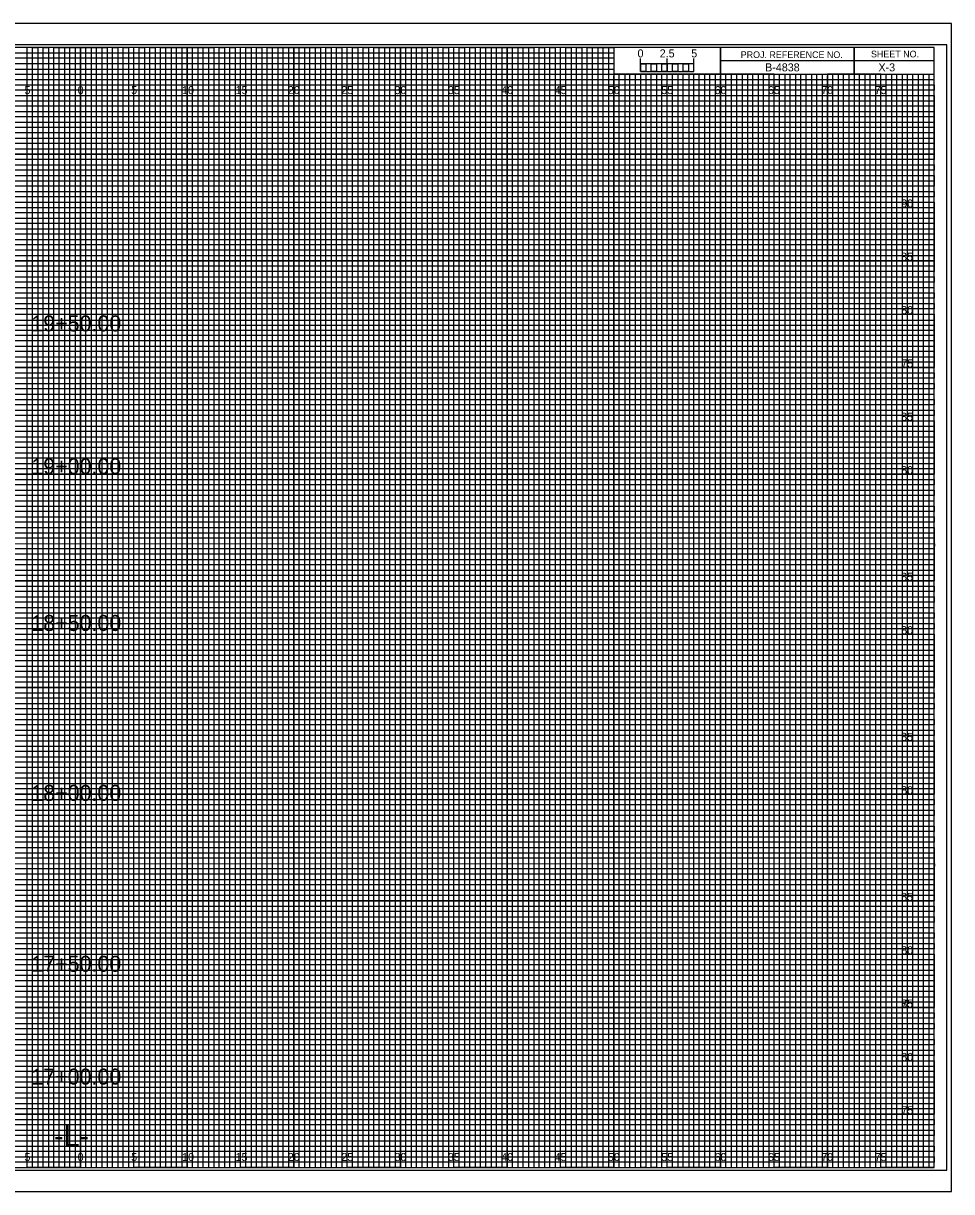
# Model space of a CAD drawing. Extents: x -7 to 182, y -2 to 1647.
# Drawn here: x 74.6 to 161.7, y 107.7 to 217.2 of the extents above; entities that cross this region are included whole.
import ezdxf

# ---------------------------------------------------------------- set-up
doc = ezdxf.new("R2010")
doc.units = 0
for name, color, linetype in [('Exist CMT Pavement', 7, 'Continuous'), ('Exist Cross Section Cell', 7, 'Continuous'), ('Exist XS Ground Line', 7, 'Continuous'), ('Prop CMT Pvmt Course 1', 7, 'Continuous'), ('Prop CMT Pvmt Course 2', 7, 'Continuous'), ('Prop CMT Pvmt Course 2 Wedge', 7, 'Continuous'), ('Prop CMT Pvmt Course 3', 7, 'Continuous'), ('Prop CMT Pvmt Surface', 7, 'Continuous'), ('Prop CMT Pvmt Surface Shoulder', 7, 'Continuous'), ('Prop CMT Pvmt Wedge Surface 1', 7, 'Continuous'), ('Prop CMT Pvmt Wedge Surface 2', 7, 'Continuous'), ('Prop CMT Pvmt Wedge Surface 3', 7, 'Continuous'), ('Prop CMT Shld Paved Course 1', 7, 'Continuous'), ('Prop CMT Shld Paved Course 2', 7, 'Continuous'), ('Prop CMT Shld Paved Course 3', 7, 'Continuous'), ('Prop CMT Slope Grass', 7, 'Continuous'), ('Prop CMT Subgrade Earthwork', 7, 'Continuous')]:
    doc.layers.add(name, color=color, linetype=linetype)

msp = doc.modelspace()

# ---------------------------------------------------------------- linework, layer by layer
at = {"layer": 'Exist XS Ground Line'}
for p, q in [((75, 215), (70, 215)), ((75, 110), (75, 215)), ((85, 215), (80, 215)), ((80, 215), (80, 110)), ((85, 110), (85, 215)), ((95, 215), (90, 215)), ((90, 215), (90, 110)), ((95, 110), (95, 215)), ((105, 215), (100, 215)), ((100, 215), (100, 110)), ((105, 110), (105, 215)), ((115, 215), (110, 215)), ((110, 215), (110, 110)), ((115, 110), (115, 215)), ((125, 215), (120, 215)), ((120, 215), (120, 110)), ((125, 110), (125, 215)), ((130, 215), (130, 110)), ((135, 110), (135, 212.5)), ((145, 212.5), (140, 212.5)), ((140, 212.5), (140, 110)), ((145, 110), (145, 212.5)), ((155, 212.5), (150, 212.5)), ((150, 212.5), (150, 110)), ((155, 110), (155, 212.5)), ((80, 110), (75, 110)), ((90, 110), (85, 110)), ((100, 110), (95, 110)), ((110, 110), (105, 110)), ((120, 110), (115, 110)), ((130, 110), (125, 110)), ((140, 110), (135, 110)), ((150, 110), (145, 110)), ((160, 110), (155, 110)), ((160, 110), (160, 110))]:
    msp.add_line(p, q, dxfattribs=at)
for points in [[(0, 210), (160, 210), (160, 205), (0, 205)], [(0, 200), (160, 200), (160, 195), (0, 195)], [(0, 190), (160, 190), (160, 185), (0, 185)], [(0, 180), (160, 180), (160, 175), (0, 175)], [(0, 170), (160, 170), (160, 165), (0, 165)], [(0, 160), (160, 160), (160, 155), (0, 155)], [(0, 150), (160, 150), (160, 145), (0, 145)], [(0, 140), (160, 140), (160, 135), (0, 135)], [(0, 130), (160, 130), (160, 125), (0, 125)], [(0, 120), (160, 120), (160, 115), (0, 115)]]:
    msp.add_lwpolyline(points, dxfattribs=at)
at = {"layer": 'Prop CMT Pvmt Course 2'}
for p, q in [((132.5, 212.75), (132.5, 213.95)), ((132.5, 213.45), (132.5, 213.95)), ((135, 212.75), (135, 213.95)), ((137.5, 212.75), (137.5, 213.95)), ((137.5, 213.45), (137.5, 213.95))]:
    msp.add_line(p, q, dxfattribs=at)
for points in [[(137.5, 213.45), (132.5, 213.45), (132.5, 212.75), (137.5, 212.75)], [(132.5, 213.45), (133, 213.45), (133, 212.75), (132.5, 212.75)], [(133.5, 213.45), (134, 213.45), (134, 212.75), (133.5, 212.75)], [(134.5, 213.45), (135, 213.45), (135, 212.75), (134.5, 212.75)], [(135.5, 213.45), (136, 213.45), (136, 212.75), (135.5, 212.75)], [(136.5, 213.45), (137, 213.45), (137, 212.75), (136.5, 212.75)]]:
    msp.add_lwpolyline(points, close=True, dxfattribs=at)
at = {"layer": 'Prop CMT Pvmt Course 3'}
msp.add_lwpolyline([(-6.7, 107.75), (161.65, 107.75), (161.65, 217.25), (-6.7, 217.25)], close=True, dxfattribs=at)
at = {"layer": 'Prop CMT Pvmt Wedge Surface 1'}
for p, q in [((0, 214.5), (130, 214.5)), ((130, 213.99), (0, 213.99)), ((130, 214.5), (130, 213.99)), ((0, 213.5), (130, 213.5)), ((130, 212.94), (0, 212.94)), ((130, 213.5), (130, 212.94)), ((0, 212), (160, 212))]:
    msp.add_line(p, q, dxfattribs=at)
for points in [[(0, 211.5), (135, 211.5), (160, 211.5), (160, 211), (0, 211)], [(0, 210.5), (160, 210.5), (160, 209.5), (0, 209.5)], [(0, 209), (160, 209), (160, 208.5), (0, 208.49)], [(0, 208), (160, 208), (160, 207), (0, 207)], [(0, 206.5), (160, 206.5), (160, 206), (0, 206)], [(0, 205.5), (160, 205.5), (160, 204.5), (0, 204.5)], [(0, 204), (160, 204), (160, 203.5), (0, 203.5)], [(0, 203), (160, 203), (160, 202), (0, 202)], [(0, 201.5), (160, 201.5), (160, 201), (0, 201)], [(0, 200.5), (160, 200.5), (160, 199.5), (0, 199.5)], [(0, 199), (160, 199), (160, 198.5), (0, 198.5)], [(0, 198), (160, 198), (160, 196.97), (160, 196.5), (160, 196), (0, 196)], [(0, 197), (160, 197), (160, 196.5), (0, 196.5)], [(0, 195.5), (160, 195.5), (160, 194.5), (0, 194.52)], [(0, 194.52), (160, 194.5), (160, 194), (0, 194)], [(0, 193.5), (160, 193.5), (160, 193), (0, 193)], [(0, 192), (160, 192), (160, 191.5), (0, 191.5)], [(0, 191), (160, 191), (160, 190.5), (0, 190.5)], [(-0.04, 189.44), (160, 189.44), (160, 188.94), (-0.04, 188.94)], [(0, 188.5), (160, 188.5), (160, 188), (0, 188)], [(0, 187), (160, 187), (160, 186.5), (0, 186.5)], [(0, 186), (160, 186), (160, 185.5), (0, 185.5)], [(0, 184.5), (160, 184.5), (160, 184), (0, 184)], [(0, 183.5), (160, 183.5), (160, 183), (0, 183)], [(0, 182), (160, 182), (160, 181.5), (0, 181.5)], [(0, 181), (160, 181), (160, 180.5), (0, 180.5)], [(0, 179.5), (160, 179.5), (160, 178.99), (0, 179)], [(0, 178.5), (160, 178.5), (160, 178), (0, 178)], [(0, 177), (160, 177), (160, 176.5), (0, 176.5)], [(0, 176), (160, 176), (160, 175.5), (0, 175.5)], [(0, 174.5), (160, 174.5), (160, 174), (0, 174)], [(0, 173.5), (160, 173.5), (160, 173), (0, 173)], [(0, 172), (160, 172), (160, 171.5), (0, 171.5)], [(0, 171), (160, 171), (160, 170.5), (0, 170.5)], [(0, 169.5), (160, 169.5), (160, 169), (0, 169)], [(0, 168.5), (160.03, 168.46), (160, 168), (0, 168)], [(0, 167), (160, 167), (160, 166.5), (0, 166.5)], [(0, 166), (160, 166), (160, 165.5), (0, 165.5)], [(0, 164.5), (160, 164.5), (160, 164), (0, 164)], [(0, 163.5), (160, 163.5), (160, 163), (0, 163)], [(0, 162), (160, 162), (160, 161.5), (0, 161.5)], [(0, 161), (160, 161), (160, 160.5), (0, 160.5)], [(0, 159.5), (160, 159.5), (160, 159), (0, 159)], [(0, 158.5), (160, 158.5), (160, 158), (0, 158)], [(0, 157), (160, 157), (160, 156.5), (0, 156.5)], [(0, 156), (160, 156), (160, 155.5), (0, 155.5)], [(0, 154.5), (160, 154.5), (160, 154), (0, 154)], [(0, 153.5), (160, 153.5), (160, 153), (0, 153)], [(0, 152), (160, 152), (160, 151.5), (0, 151.5)], [(0, 151), (160, 151), (160, 150.5), (0, 150.5)], [(0, 149.5), (160, 149.5), (160, 148.99), (0, 149)], [(0, 148.5), (160, 148.5), (160, 148), (0, 148)], [(0, 147), (160, 147), (160, 146.5), (0, 146.5)], [(0, 146), (160, 146), (160, 145.5), (0, 145.5)], [(0, 144.5), (160, 144.5), (160, 144), (0, 144)], [(0, 143.5), (160, 143.5), (160, 143), (0, 143)], [(0, 142), (160, 142), (160, 141.5), (0, 141.5)], [(0, 141), (160, 141), (160, 140.5), (0, 140.5)], [(0, 139.5), (160, 139.5), (160, 139), (0, 139)], [(0, 138.5), (160.03, 138.46), (160, 138), (0, 138)], [(0, 137), (160, 137), (160, 136.5), (0, 136.5)], [(0, 136), (160, 136), (160, 135.5), (0, 135.5)], [(0, 134.5), (160, 134.5), (160, 134), (0, 134)], [(0, 133.5), (160, 133.5), (160, 133), (0, 133)], [(0, 132), (160, 132), (160, 131.5), (0, 131.5)], [(0, 131), (160, 131), (160, 130.5), (0, 130.5)], [(0, 129.5), (160, 129.5), (160, 129), (0, 129)], [(0, 128.5), (160, 128.5), (160, 128), (0, 128)], [(0, 127), (160, 127), (160, 126.5), (0, 126.5)], [(0, 126), (160, 126), (160, 125.5), (0, 125.5)], [(0, 124.5), (160, 124.5), (160, 124), (0, 124)], [(0, 123.5), (160, 123.5), (160, 123), (0, 123)], [(0, 122), (160, 122), (160, 121.5), (0, 121.5)], [(0, 121), (160, 121), (160, 120.5), (0, 120.5)], [(0, 119.5), (160, 119.5), (160, 119), (0, 119)], [(0, 118.5), (160, 118.5), (160, 118), (0, 118)], [(0, 117), (160, 117), (160, 116.5), (0, 116.5)], [(0, 116), (160, 116), (160, 115.5), (0, 115.5)], [(0, 114.5), (160, 114.5), (160, 114), (0, 114)], [(0, 113.5), (160, 113.5), (160, 113), (0, 113)], [(0, 112), (160, 112), (160, 111.5), (0, 111.5)], [(0, 111), (160, 111), (160, 110.5), (0, 110.5)]]:
    msp.add_lwpolyline(points, dxfattribs=at)
at = {"layer": 'Prop CMT Pvmt Wedge Surface 2'}
for p, q in [((152.5, 215), (152.5, 212.5)), ((152.5, 212.5), (152.5, 215)), ((160, 213.75), (140, 213.75)), ((140, 213.75), (140, 212.5)), ((140, 212.5), (160, 212.5))]:
    msp.add_line(p, q, dxfattribs=at)
for points in [[(160, 215), (0, 215), (0, 110), (160, 110)], [(140, 215), (130, 215), (130, 212.52), (140, 212.52)], [(160, 215), (140, 215), (140, 212.5), (160, 212.5)]]:
    msp.add_lwpolyline(points, close=True, dxfattribs=at)
at = {"layer": 'Prop CMT Pvmt Wedge Surface 3'}
for p, q in [((133.5, 212.5), (133, 212.5)), ((133, 212.5), (133, 110)), ((133.5, 110), (133.5, 212.5)), ((134.5, 212.5), (134, 212.5)), ((134, 212.5), (134, 110)), ((134.5, 110), (134.5, 212.5)), ((133, 110), (132.5, 110)), ((134, 110), (133.5, 110))]:
    msp.add_line(p, q, dxfattribs=at)
for points in [[(75, 110), (75.5, 110), (75.5, 215), (76, 215), (76, 110)], [(76, 110), (76.5, 110), (76.5, 215), (77, 215), (77, 110)], [(77.5, 110), (78, 110), (78, 215), (78.5, 215), (78.5, 110)], [(78.5, 110), (79, 110), (79, 215), (79.5, 215), (79.5, 110)], [(80, 110), (80.5, 110), (80.5, 215), (81, 215), (81, 110)], [(81, 110), (81.5, 110), (81.5, 215), (82, 215), (82, 110)], [(82.5, 110), (83, 110), (83, 215), (83.5, 215), (83.5, 110)], [(83.5, 110), (84, 110), (84, 215), (84.5, 215), (84.5, 110)], [(85, 110), (85.5, 110), (85.5, 215), (86, 215), (86, 110)], [(86, 110), (86.5, 110), (86.5, 215), (87, 215), (87, 110)], [(87.5, 110), (88, 110), (88, 215), (88.5, 215), (88.5, 110)], [(88.5, 110), (89, 110), (89, 215), (89.5, 215), (89.5, 110)], [(90, 110), (90.5, 110), (90.5, 215), (91, 215), (91, 110)], [(91, 110), (91.5, 110), (91.5, 215), (92, 215), (92, 110)], [(92.5, 110), (93, 110), (93, 215), (93.5, 215), (93.5, 110)], [(93.5, 110), (94, 110), (94, 215), (94.5, 215), (94.5, 110)], [(95, 110), (95.5, 110), (95.5, 215), (96, 215), (96, 110)], [(96, 110), (96.5, 110), (96.5, 215), (97, 215), (97, 110)], [(97.5, 110), (98, 110), (98, 215), (98.5, 215), (98.5, 110)], [(98.5, 110), (99, 110), (99, 215), (99.5, 215), (99.5, 110)], [(100, 110), (100.5, 110), (100.5, 215), (101, 215), (101, 110)], [(101, 110), (101.5, 110), (101.5, 215), (102, 215), (102, 110)], [(102.5, 110), (103, 110), (103, 215), (103.5, 215), (103.5, 110)], [(103.5, 110), (104, 110), (104, 215), (104.5, 215), (104.5, 110)], [(105, 110), (105.5, 110), (105.5, 215), (106, 215), (106, 110)], [(106, 110), (106.5, 110), (106.5, 215), (107, 215), (107, 110)], [(107.5, 110), (108, 110), (108, 215), (108.5, 215), (108.5, 110)], [(108.5, 110), (109, 110), (109, 215), (109.5, 215), (109.5, 110)], [(110, 110), (110.5, 110), (110.5, 215), (111, 215), (111, 110)], [(111, 110), (111.5, 110), (111.5, 215), (112, 215), (112, 110)], [(112.5, 110), (113, 110), (113, 215), (113.5, 215), (113.5, 110)], [(113.5, 110), (114, 110), (114, 215), (114.5, 215), (114.5, 110)], [(115, 110), (115.5, 110), (115.5, 215), (116, 215), (116, 110)], [(116, 110), (116.5, 110), (116.5, 215), (117, 215), (117, 110)], [(117.5, 110), (118, 110), (118, 215), (118.5, 215), (118.5, 110)], [(118.5, 110), (119, 110), (119, 215), (119.5, 215), (119.5, 110)], [(120, 110), (120.5, 110), (120.5, 215), (121, 215), (121, 110)], [(121, 110), (121.5, 110), (121.5, 215), (122, 215), (122, 110)], [(122.5, 110), (123, 110), (123, 215), (123.5, 215), (123.5, 110)], [(123.5, 110), (124, 110), (124, 215), (124.5, 215), (124.5, 110)], [(125, 110), (125.5, 110), (125.5, 215), (126, 215), (126, 110)], [(126, 110), (126.5, 110), (126.5, 215), (127, 215), (127, 110)], [(127.5, 110), (128, 110), (128, 215), (128.5, 215), (128.5, 110)], [(128.5, 110), (129, 110), (129, 215), (129.5, 215), (129.5, 110)], [(130, 110), (130.5, 110), (130.5, 212.5), (131.01, 212.5), (131.01, 110)], [(131, 110), (131.5, 110), (131.5, 212.5), (132, 212.5), (132, 110)], [(135, 110), (135.49, 110), (135.49, 212.5), (136, 212.5), (136, 110)], [(136, 110), (136.5, 110), (136.5, 212.5), (137.03, 212.5), (137.03, 110)], [(137.5, 110), (138, 110), (138, 212.5), (138.5, 212.5), (138.5, 110)], [(138.5, 110), (139, 110), (139, 212.5), (139.5, 212.5), (139.5, 110)], [(140, 110), (140.5, 110), (140.5, 212.5), (141, 212.5), (141, 110)], [(141, 110), (141.5, 110), (141.5, 212.5), (142, 212.5), (142, 110)], [(142.5, 110), (143, 110), (143, 212.5), (143.5, 212.5), (143.5, 110)], [(143.5, 110), (144, 110), (144, 212.5), (144.5, 212.5), (144.5, 110)], [(145, 110), (145.5, 110), (145.5, 212.5), (146, 212.5), (146, 110)], [(146, 110), (146.5, 110), (146.5, 212.5), (147, 212.5), (147, 110)], [(147.5, 110), (148, 110), (148, 212.5), (148.5, 212.5), (148.5, 110)], [(148.5, 110), (149, 110), (149, 212.5), (149.5, 212.5), (149.5, 110)], [(150, 110), (150.5, 110), (150.5, 212.5), (151, 212.5), (151, 110)], [(151, 110), (151.5, 110), (151.5, 212.5), (152, 212.5), (152, 110)], [(152.5, 110), (153, 110), (153, 212.5), (153.5, 212.5), (153.5, 110)], [(153.5, 110), (154, 110), (154, 212.5), (154.5, 212.5), (154.5, 110)], [(155, 110), (155.5, 110), (155.5, 212.5), (156, 212.5), (156, 110)], [(156, 110), (156.5, 110), (156.5, 212.5), (157, 212.5), (157, 110)], [(157.5, 110), (158, 110), (158, 212.5), (158.5, 212.5), (158.5, 110)], [(158.5, 110), (159, 110), (159, 212.5), (159.5, 212.5), (159.5, 110)]]:
    msp.add_lwpolyline(points, dxfattribs=at)
at = {"layer": 'Prop CMT Shld Paved Course 1'}
for p, q in [((75, 110), (75, 215)), ((80, 110), (80, 215)), ((85, 110), (85, 215)), ((90, 110), (90, 215)), ((95, 110), (95, 215)), ((100, 110), (100, 215)), ((105, 110), (105, 215)), ((110, 110), (110, 215)), ((115, 110), (115, 215)), ((120, 110), (120, 215)), ((125, 110), (125, 215)), ((130, 110), (130, 212.34)), ((135, 110), (135, 212.34)), ((140, 110), (140, 212.34)), ((145, 110), (145, 212.34)), ((150, 110), (150, 212.34)), ((155, 110), (155, 212.34)), ((0, 210), (160, 210)), ((0, 205), (160, 205)), ((0, 200), (160, 200)), ((0, 195), (160, 195)), ((0, 190), (160, 190)), ((0, 185), (160, 185)), ((0, 180), (160, 180)), ((0, 175), (160, 175)), ((0, 170), (160, 170)), ((0, 165), (160, 165)), ((0, 160), (160, 160)), ((0, 155), (160, 155)), ((0, 150), (160, 150)), ((0, 145), (160, 145)), ((0, 140), (160, 140)), ((0, 135), (160, 135)), ((0, 130), (160, 130)), ((0, 125), (160, 125)), ((0, 120), (160, 120)), ((0, 115), (160, 115))]:
    msp.add_line(p, q, dxfattribs=at)
at = {"layer": 'Prop CMT Shld Paved Course 2'}
for p, q in [((161.65, 217.25), (-6.7, 217.25)), ((-6.7, 107.75), (161.65, 107.75))]:
    msp.add_line(p, q, dxfattribs=at)
at = {"layer": 'Prop CMT Slope Grass'}
msp.add_lwpolyline([(-5.4, 109.75), (161.2, 109.75), (161.2, 215.25), (-5.4, 215.25)], close=True, dxfattribs=at)
at = {"layer": 'Prop CMT Subgrade Earthwork'}
for points in [[(72.5, 110), (77.5, 110), (77.5, 215), (82.5, 215), (82.5, 110), (87.5, 110), (87.5, 215), (92.5, 215), (92.5, 110), (97.5, 110), (97.5, 215), (102.5, 215), (102.5, 110), (107.5, 110), (107.5, 215), (112.5, 215), (112.5, 110), (117.5, 110), (117.5, 215), (122.5, 215), (122.5, 110), (127.5, 110), (127.5, 215), (129.97, 215), (130, 215), (130, 212.5), (132.5, 212.5), (132.5, 110), (137.5, 110), (137.5, 212.5), (142.5, 212.5), (142.5, 110), (147.5, 110), (147.5, 212.5), (152.5, 212.5), (152.5, 110), (157.5, 110), (157.5, 212.5)], [(0, 212.5), (137.5, 212.5)], [(0, 202.5), (160, 202.5), (160, 207.5), (0, 207.5)], [(0, 192.5), (160, 192.5), (160, 197.5), (0, 197.5)], [(0, 182.5), (160, 182.5), (160, 187.5), (0, 187.5)], [(0, 172.5), (160, 172.5), (160, 177.5), (0, 177.5)], [(0, 162.5), (160, 162.5), (160, 167.5), (0, 167.5)], [(0, 152.5), (160, 152.5), (160, 157.5), (0, 157.5)], [(0, 142.5), (160, 142.5), (160, 147.5), (0, 147.5)], [(0, 132.5), (160, 132.5), (160, 137.5), (0, 137.5)], [(0, 122.5), (160, 122.5), (160, 127.5), (0, 127.5)], [(0, 112.5), (160, 112.5), (160, 117.5), (0, 117.5)]]:
    msp.add_lwpolyline(points, dxfattribs=at)

# ---------------------------------------------------------------- texts
at = {"layer": 'Exist CMT Pavement'}
for s, p in [('19+50.00', (75.39, 188.38)), ('19+00.00', (75.39, 174.99)), ('18+50.00', (75.39, 160.3)), ('18+00.00', (75.39, 144.37)), ('17+50.00', (75.39, 128.36)), ('17+00.00', (75.39, 117.78))]:
    msp.add_text(s, height=1.5, dxfattribs=at).set_placement(p)
at = {"layer": 'Exist Cross Section Cell'}
for s, p in [('5', (74.74, 210.62)), ('0', (79.73, 210.62)), ('0', (79.73, 210.62)), ('5', (84.74, 210.62)), ('10', (89.52, 210.62)), ('15', (94.53, 210.62)), ('20', (99.43, 210.62)), ('25', (104.44, 210.62)), ('30', (109.43, 210.62)), ('35', (114.44, 210.62)), ('40', (119.43, 210.62)), ('45', (124.44, 210.62)), ('50', (129.43, 210.62)), ('55', (134.44, 210.62)), ('60', (139.43, 210.62)), ('65', (144.44, 210.62)), ('70', (149.43, 210.62)), ('75', (154.44, 210.62)), ('5', (74.74, 110.62)), ('0', (79.73, 110.62)), ('0', (79.73, 110.62)), ('5', (84.74, 110.62)), ('10', (89.52, 110.62)), ('15', (94.53, 110.62)), ('20', (99.43, 110.62)), ('25', (104.44, 110.62)), ('30', (109.43, 110.62)), ('35', (114.44, 110.62)), ('40', (119.43, 110.62)), ('45', (124.44, 110.62)), ('50', (129.43, 110.62)), ('55', (134.44, 110.62)), ('60', (139.43, 110.62)), ('65', (144.44, 110.62)), ('70', (149.43, 110.62)), ('75', (154.44, 110.62))]:
    msp.add_text(s, height=0.75, dxfattribs=at).set_placement(p)
at = {"layer": 'Prop CMT Pvmt Course 1'}
msp.add_text('-L-', height=2, dxfattribs=at).set_placement((77.53, 112))
at = {"layer": 'Prop CMT Pvmt Course 2'}
msp.add_text('0', height=0.75, dxfattribs=at).set_placement((132.21, 214.06))
at = {"layer": 'Prop CMT Pvmt Course 2 Wedge'}
for s, p in [('2.5', (134.29, 214.06)), ('5', (137.24, 214.06))]:
    msp.add_text(s, height=0.75, dxfattribs=at).set_placement(p)
at = {"layer": 'Prop CMT Pvmt Surface'}
msp.add_text('X-3', height=0.75, dxfattribs=at).set_placement((154.79, 212.75))
at = {"layer": 'Prop CMT Pvmt Surface Shoulder'}
msp.add_text('B-4838', height=0.75, dxfattribs=at).set_placement((144.17, 212.75))
at = {"layer": 'Prop CMT Pvmt Wedge Surface 2'}
for s, p in [('PROJ. REFERENCE NO.', (141.88, 214)), ('SHEET NO.', (154.09, 214.06))]:
    msp.add_text(s, height=0.625, dxfattribs=at).set_placement(p)
at = {"layer": 'Prop CMT Shld Paved Course 3'}
for s, p in [('90', (156.93, 200)), ('85', (156.91, 195)), ('80', (156.92, 190)), ('75', (156.94, 185)), ('85', (156.91, 180)), ('80', (156.92, 175)), ('85', (156.91, 165)), ('80', (156.92, 160)), ('85', (156.91, 150)), ('80', (156.92, 145)), ('85', (156.91, 135)), ('80', (156.92, 130)), ('85', (156.91, 125)), ('75', (156.94, 125)), ('80', (156.92, 120)), ('75', (156.94, 115))]:
    msp.add_text(s, height=0.75, dxfattribs=at).set_placement(p)

doc.saveas('drawing.dxf')
